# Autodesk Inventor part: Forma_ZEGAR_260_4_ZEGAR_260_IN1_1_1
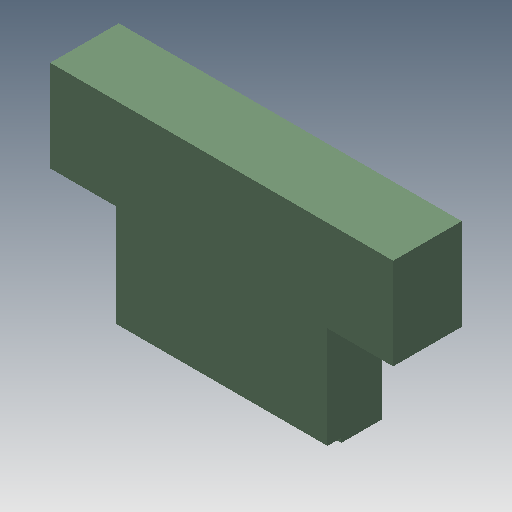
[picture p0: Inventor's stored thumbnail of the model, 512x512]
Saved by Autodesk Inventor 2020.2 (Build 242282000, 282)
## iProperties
Created: 2015-01
Part Number: Forma_ZEGAR_260_4_ZEGAR_260_IN1_1_1
Material: Ogólny
Document SubType Name: Modeling
Designer: F.Stasiak
Density: 1 g/cm^3
Appearance: Domyślna
Catalog Web Link: www.expertbooks.pl
Manager: www.cadconsulting.pl
Company: Fabian Stasiak CAD Consulting
Author: F.Stasiak
Subject: Zbiór ćwiczeń. Autodesk Inventor 2020. Kurs Professional
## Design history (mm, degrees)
node "Forma_ZEGAR_260_4_ZEGAR_260_IN1_Base"
feature "Bryła1::Forma_ZEGAR_260_4_ZEGAR_260_IN1_Base"
tag "Bryła wyprowadzona1"
node "Bryła1"
feature "Forma_ZEGAR_260_4_ZEGAR_260_IN1_Base_Bodies"
